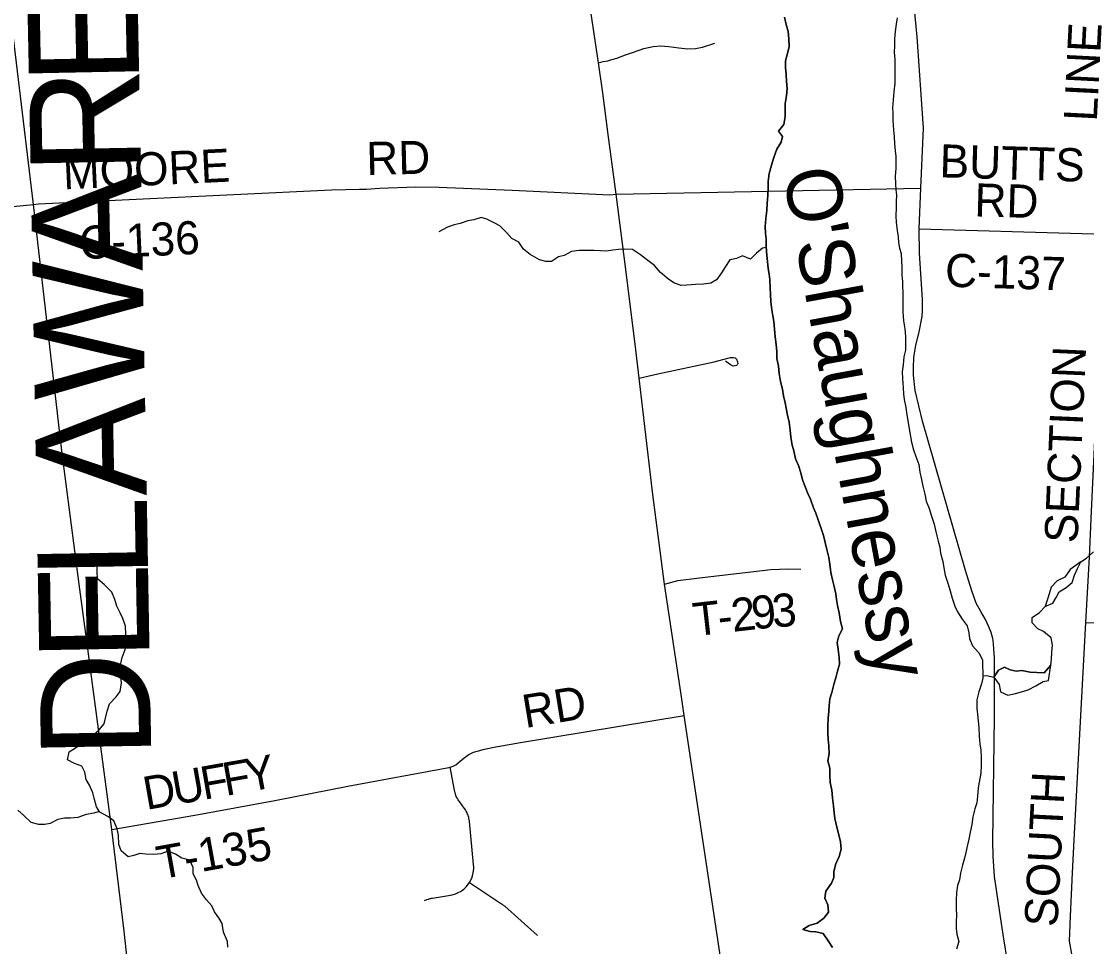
# Model space of a CAD drawing. Extents: x 114843 to 284848, y 317643 to 566895.
# Drawn here: x 158973 to 168629, y 472931 to 481317 of the extents above; entities that cross this region are included whole.
import ezdxf

# ---------------------------------------------------------------- set-up
doc = ezdxf.new("R2010")
doc.units = 0
for name, color, linetype in [('GM_X_County_Road', 7, 'Continuous'), ('GM_X_County_Road_Text', 7, 'Continuous'), ('GM_X_County_Text', 7, 'Continuous'), ('GM_X_Major_Lake', 7, 'Continuous'), ('GM_X_Major_Lake_Text', 7, 'Continuous'), ('GM_X_Major_River', 7, 'Continuous'), ('GM_X_Minor_Lake', 7, 'Continuous'), ('GM_X_Minor_River', 7, 'Continuous'), ('GM_X_State_Route', 7, 'Continuous'), ('GM_X_Township_Road', 7, 'Continuous'), ('GM_X_Township_Road_Text', 7, 'Continuous')]:
    doc.layers.add(name, color=color, linetype=linetype)

msp = doc.modelspace()

# ---------------------------------------------------------------- linework, layer by layer
at = {"layer": 'GM_X_County_Road'}
msp.add_line((164365.2, 479750.2), (167125.8, 479806.3), dxfattribs=at)
for points in [[(159995.6, 472237.1), (159989.5, 472274.8), (159966.4, 472511.4), (159905.9, 473072.7), (159793.2, 473994.7), (159569.3, 475675.8), (159495.8, 476217.3), (159338.5, 477426), (159082.2, 479658.2), (158724.2, 482628.7), (158714, 482659), (158704.8, 482681.5), (158690.1, 482700.8)], [(157972.4, 479547.1), (158895.2, 479640), (159082.2, 479658.2), (159128.7, 479662.1), (161782.7, 479788.9), (162037.7, 479794.5), (162101.2, 479797.4), (162218.7, 479806.1), (162549.4, 479817.5), (162760.8, 479813.2), (163422.3, 479788.3), (164307.3, 479746), (164365.2, 479750.2)], [(167111, 479436.1), (168587.6, 479394.1), (168791.8, 479386.9)], [(168500.2, 472699.2), (168497.8, 472847.6), (168474.7, 472980.9), (168482.2, 473208.2), (168501.7, 473600.7), (168517.9, 473957), (168621, 475870.1), (168654.6, 476460.9), (168672.4, 476876.8), (168748.3, 478484), (168750.7, 478520.2), (168757.1, 478618.5), (168791.8, 479386.9)]]:
    msp.add_lwpolyline(points, dxfattribs=at)
at = {"layer": 'GM_X_Major_Lake'}
for points in [[(166369, 475687), (166382.9, 475749.2), (166414.8, 475811.4), (166398.6, 475879.5), (166384.3, 475957.6), (166370.1, 476021.7), (166361.9, 476077.7), (166355.7, 476129.8), (166341.5, 476195.9), (166325.3, 476256), (166311.1, 476322.1), (166300.8, 476398.2), (166290.6, 476458.3), (166274.4, 476530.4), (166258.1, 476594.4), (166243.9, 476658.5), (166225.7, 476712.6), (166201.5, 476780.7), (166173.2, 476858.7), (166153, 476908.8), (166124.7, 476986.9), (166102.5, 477038.9), (166080.2, 477093), (166054, 477163), (166037.7, 477225.1), (166017.5, 477291.2), (165991.3, 477353.2), (165975, 477425.4), (165960.8, 477475.4), (165948.6, 477547.5), (165940.4, 477611.6), (165932.1, 477685.8), (165917.9, 477747.9), (165905.7, 477809.9), (165897.5, 477860), (165881.3, 477924.1), (165871.1, 477984.2), (165854.9, 478054.3), (165842.6, 478124.4), (165834.4, 478190.5), (165822.2, 478262.7), (165820, 478322.8), (165815.8, 478388.9), (165805.6, 478459), (165799.3, 478527.2), (165793.1, 478597.3), (165783, 478649.4), (165774.8, 478701.5), (165766.5, 478775.6), (165762.3, 478845.7), (165760.2, 478897.8), (165757.9, 478976), (165751.8, 479026.1), (165741.6, 479078.2), (165737.4, 479140.3), (165731.2, 479194.4), (165725, 479276.5), (165722.8, 479344.7), (165718.6, 479394.8), (165716.4, 479456.9), (165722.2, 479531.1), (165730.1, 479601.2), (165731.9, 479667.4), (165737.7, 479737.5), (165743.5, 479801.7), (165743.3, 479865.8), (165751.1, 479938), (165773, 480012.2), (165794.8, 480082.4), (165820.7, 480158.7), (165858.6, 480220.9), (165872.5, 480273), (165836.2, 480323), (165884.2, 480383.3), (165896, 480453.5), (165895.9, 480503.6), (165897.7, 480571.7), (165907.5, 480641.9), (165913.3, 480708.1), (165909.1, 480774.2), (165904.9, 480834.3), (165900.7, 480898.4), (165900.6, 480958.6), (165916.4, 481024.8), (165932.3, 481088.9), (165930.1, 481159.1), (165923.8, 481225.2), (165905.6, 481289.3), (165889.4, 481353.4)], [(166910.1, 481348), (166902.3, 481289.8), (166894.4, 481225.7), (166888.6, 481157.5), (166886.8, 481091.4), (166884.9, 481037.2), (166889.1, 480971.1), (166891.3, 480909), (166891.6, 480808.8), (166889.8, 480756.7), (166882, 480676.5), (166876.2, 480606.3), (166870.4, 480534.1), (166872.5, 480484), (166872.7, 480417.9), (166877, 480333.7), (166885.2, 480271.6), (166887.4, 480205.5), (166893.6, 480143.3), (166899.7, 480091.2), (166899.9, 480035.1), (166898.1, 479983), (166894.2, 479912.8), (166896.4, 479844.7), (166898.6, 479790.6), (166904.8, 479740.5), (166902.9, 479684.4), (166901.1, 479632.3), (166899.3, 479550.1), (166903.5, 479498), (166911.7, 479421.8), (166919.9, 479363.7), (166924.1, 479313.6), (166932.2, 479261.6), (166946.4, 479211.5), (166950.6, 479143.3), (166954.8, 479091.2), (166955, 479019.1), (166961.2, 478957), (166961.6, 478822.7), (166963.7, 478768.6), (166962, 478688.4), (166968.2, 478602.3), (166980.5, 478530.1), (166986.7, 478460), (166987.1, 478335.8), (166973.2, 478275.6), (166965.4, 478203.4), (166957.5, 478141.3), (166959.7, 478079.1), (166966, 477997), (166968.2, 477940.9), (166974.3, 477888.8), (166988.6, 477818.7), (166998.8, 477750.6), (167011, 477682.5), (167019.2, 477624.4), (167031.4, 477554.3), (167041.6, 477502.2), (167059.9, 477434.1), (167080.1, 477372), (167108.4, 477299.9), (167116.6, 477231.8), (167132.8, 477163.8), (167145, 477103.7), (167161.3, 477031.6), (167175.5, 476967.5), (167201.8, 476903.4), (167224, 476831.3)], [(167224, 476831.3), (167246.3, 476761.2), (167258.5, 476707.2), (167270.7, 476655.1), (167282.8, 476605), (167297, 476553), (167305.2, 476496.9), (167325.5, 476422.8), (167335.7, 476364.7), (167345.9, 476298.6), (167370.2, 476224.5), (167390.4, 476156.5), (167408.7, 476088.4), (167434.9, 476016.3), (167457.1, 475964.3), (167499.4, 475900.3), (167545.7, 475838.3), (167562, 475774.2), (167568.1, 475724.1), (167594.4, 475658.1), (167652.7, 475594.1), (167685, 475530.1), (167685.1, 475472), (167689.3, 475417.9), (167687.5, 475363.8), (167675.6, 475313.7), (167651.7, 475239.5), (167633.9, 475167.3), (167634.1, 475089.2), (167638.3, 475037.1), (167646.5, 474975), (167652.6, 474916.9), (167654.9, 474838.8), (167661.1, 474766.7), (167669.2, 474714.6), (167671.4, 474642.5), (167671.6, 474576.4), (167669.8, 474504.3), (167656, 474422.2), (167646.1, 474370), (167640.3, 474295.9), (167632.5, 474235.8), (167614.6, 474179.7), (167596.8, 474107.5), (167586.9, 474037.4), (167573.1, 473969.3), (167561.2, 473905.2), (167549.3, 473853), (167533.5, 473784.9), (167521.6, 473734.8), (167503.7, 473668.7), (167485.9, 473598.5), (167476, 473536.4), (167458.1, 473486.3), (167450.3, 473422.2), (167446.5, 473350.1), (167446.7, 473280), (167448.8, 473211.9), (167447, 473161.9), (167447.2, 473095.8), (167451.3, 473043.7), (167471.5, 472979.7), (167449.7, 472907.6)], [(166324.6, 472924.8), (166286.4, 472984.8), (166242.1, 473050.7), (166173.9, 473066.6), (166123.7, 473068.5), (166057.5, 473086.3), (166113.5, 473122.5), (166185.7, 473144.7), (166245.7, 473188.9), (166289.7, 473243.1), (166281.5, 473309.2), (166257.2, 473371.2), (166265.1, 473435.3), (166317, 473505.5), (166336.9, 473559.6), (166336.8, 473611.7), (166354.6, 473681.8), (166386.5, 473748), (166402.4, 473816.1), (166398.2, 473882.2), (166382, 473946.3), (166363.7, 474014.3), (166345.5, 474092.4), (166339.3, 474144.5), (166333.1, 474208.5), (166324.9, 474280.6), (166318.7, 474348.7), (166304.4, 474418.8), (166300.3, 474480.9), (166302.1, 474549), (166283.8, 474615), (166293.7, 474683.2), (166293.5, 474747.3), (166287.3, 474811.4), (166283.1, 474863.4), (166283, 474929.5), (166284.8, 475001.7), (166290.6, 475065.8), (166294.5, 475115.9), (166302.3, 475178), (166318.2, 475234.1), (166338, 475306.3), (166359.9, 475378.5), (166371.8, 475428.6), (166387.6, 475490.8), (166385.5, 475552.9), (166377.2, 475623), (166369, 475687)]]:
    msp.add_lwpolyline(points, dxfattribs=at)
at = {"layer": 'GM_X_Major_River'}
for points in [[(165889.4, 481353.4), (165905.6, 481289.3), (165923.8, 481225.2), (165930.1, 481159.1), (165932.3, 481088.9), (165916.4, 481024.8), (165900.6, 480958.6), (165900.7, 480898.4), (165904.9, 480834.3), (165909.1, 480774.2), (165913.3, 480708.1), (165907.5, 480641.9), (165897.7, 480571.7), (165895.9, 480503.6), (165896, 480453.5), (165884.2, 480383.3), (165836.2, 480323), (165872.5, 480273), (165858.6, 480220.9), (165820.7, 480158.7), (165794.8, 480082.4), (165773, 480012.2), (165751.1, 479938), (165743.3, 479865.8), (165743.5, 479801.7), (165737.7, 479737.5), (165731.9, 479667.4), (165730.1, 479601.2), (165722.2, 479531.1), (165716.4, 479456.9), (165718.6, 479394.8), (165722.8, 479344.7), (165725, 479276.5), (165731.2, 479194.4), (165737.4, 479140.3), (165741.6, 479078.2), (165751.8, 479026.1), (165757.9, 478976), (165760.2, 478897.8), (165762.3, 478845.7), (165766.5, 478775.6), (165774.8, 478701.5), (165783, 478649.4), (165793.1, 478597.3), (165799.3, 478527.2), (165805.6, 478459), (165815.8, 478388.9), (165820, 478322.8), (165822.2, 478262.7), (165834.4, 478190.5), (165842.6, 478124.4), (165854.9, 478054.3), (165871.1, 477984.2), (165881.3, 477924.1), (165897.5, 477860), (165905.7, 477809.9), (165917.9, 477747.9), (165932.1, 477685.8), (165940.4, 477611.6), (165948.6, 477547.5), (165960.8, 477475.4), (165975, 477425.4), (165991.3, 477353.2), (166017.5, 477291.2), (166037.7, 477225.1), (166054, 477163), (166080.2, 477093), (166102.5, 477038.9), (166124.7, 476986.9), (166153, 476908.8), (166173.2, 476858.7), (166201.5, 476780.7), (166225.7, 476712.6), (166243.9, 476658.5), (166258.1, 476594.4), (166274.4, 476530.4), (166290.6, 476458.3), (166300.8, 476398.2), (166311.1, 476322.1), (166325.3, 476256), (166341.5, 476195.9), (166355.7, 476129.8), (166361.9, 476077.7), (166370.1, 476021.7), (166384.3, 475957.6), (166398.6, 475879.5), (166414.8, 475811.4), (166382.9, 475749.2), (166369, 475687)], [(166910.1, 481348), (166902.3, 481289.8), (166894.4, 481225.7), (166888.6, 481157.5), (166886.8, 481091.4), (166884.9, 481037.2), (166889.1, 480971.1), (166891.3, 480909), (166891.6, 480808.8), (166889.8, 480756.7), (166882, 480676.5), (166876.2, 480606.3), (166870.4, 480534.1), (166872.5, 480484), (166872.7, 480417.9), (166877, 480333.7), (166885.2, 480271.6), (166887.4, 480205.5), (166893.6, 480143.3), (166899.7, 480091.2), (166899.9, 480035.1), (166898.1, 479983), (166894.2, 479912.8), (166896.4, 479844.7), (166898.6, 479790.6), (166904.8, 479740.5), (166902.9, 479684.4), (166901.1, 479632.3), (166899.3, 479550.1), (166903.5, 479498), (166911.7, 479421.8), (166919.9, 479363.7), (166924.1, 479313.6), (166932.2, 479261.6), (166946.4, 479211.5), (166950.6, 479143.3), (166954.8, 479091.2), (166955, 479019.1), (166961.2, 478957), (166961.6, 478822.7), (166963.7, 478768.6), (166962, 478688.4), (166968.2, 478602.3), (166980.5, 478530.1), (166986.7, 478460), (166987.1, 478335.8), (166973.2, 478275.6), (166965.4, 478203.4), (166957.5, 478141.3), (166959.7, 478079.1), (166966, 477997), (166968.2, 477940.9), (166974.3, 477888.8), (166988.6, 477818.7), (166998.8, 477750.6), (167011, 477682.5), (167019.2, 477624.4), (167031.4, 477554.3), (167041.6, 477502.2), (167059.9, 477434.1), (167080.1, 477372), (167108.4, 477299.9), (167116.6, 477231.8), (167132.8, 477163.8), (167145, 477103.7), (167161.3, 477031.6), (167175.5, 476967.5), (167201.8, 476903.4), (167224, 476831.3)], [(167224, 476831.3), (167246.3, 476761.2), (167258.5, 476707.2), (167270.7, 476655.1), (167282.8, 476605), (167297, 476553), (167305.2, 476496.9), (167325.5, 476422.8), (167335.7, 476364.7), (167345.9, 476298.6), (167370.2, 476224.5), (167390.4, 476156.5), (167408.7, 476088.4), (167434.9, 476016.3), (167457.1, 475964.3), (167499.4, 475900.3), (167545.7, 475838.3), (167562, 475774.2), (167568.1, 475724.1), (167594.4, 475658.1), (167652.7, 475594.1), (167685, 475530.1), (167685.1, 475472), (167689.3, 475417.9), (167687.5, 475363.8), (167675.6, 475313.7), (167651.7, 475239.5), (167633.9, 475167.3), (167634.1, 475089.2), (167638.3, 475037.1), (167646.5, 474975), (167652.6, 474916.9), (167654.9, 474838.8), (167661.1, 474766.7), (167669.2, 474714.6), (167671.4, 474642.5), (167671.6, 474576.4), (167669.8, 474504.3), (167656, 474422.2), (167646.1, 474370), (167640.3, 474295.9), (167632.5, 474235.8), (167614.6, 474179.7), (167596.8, 474107.5), (167586.9, 474037.4), (167573.1, 473969.3), (167561.2, 473905.2), (167549.3, 473853), (167533.5, 473784.9), (167521.6, 473734.8), (167503.7, 473668.7), (167485.9, 473598.5), (167476, 473536.4), (167458.1, 473486.3), (167450.3, 473422.2), (167446.5, 473350.1), (167446.7, 473280), (167448.8, 473211.9), (167447, 473161.9), (167447.2, 473095.8), (167451.3, 473043.7), (167471.5, 472979.7), (167449.7, 472907.6)], [(166369, 475687), (166377.2, 475623), (166385.5, 475552.9), (166387.6, 475490.8), (166371.8, 475428.6), (166359.9, 475378.5), (166338, 475306.3), (166318.2, 475234.1), (166302.3, 475178), (166294.5, 475115.9), (166290.6, 475065.8), (166284.8, 475001.7), (166283, 474929.5), (166283.1, 474863.4), (166287.3, 474811.4), (166293.5, 474747.3), (166293.7, 474683.2), (166283.8, 474615), (166302.1, 474549), (166300.3, 474480.9), (166304.4, 474418.8), (166318.7, 474348.7), (166324.9, 474280.6), (166333.1, 474208.5), (166339.3, 474144.5), (166345.5, 474092.4), (166363.7, 474014.3), (166382, 473946.3), (166398.2, 473882.2), (166402.4, 473816.1), (166386.5, 473748), (166354.6, 473681.8), (166336.8, 473611.7), (166336.9, 473559.6), (166317, 473505.5), (166265.1, 473435.3), (166257.2, 473371.2), (166281.5, 473309.2), (166289.7, 473243.1), (166245.7, 473188.9), (166185.7, 473144.7), (166113.5, 473122.5), (166057.5, 473086.3), (166123.7, 473068.5), (166173.9, 473066.6), (166242.1, 473050.7), (166286.4, 472984.8), (166324.6, 472924.8)]]:
    msp.add_lwpolyline(points, dxfattribs=at)
at = {"layer": 'GM_X_Minor_Lake'}
for points in [[(168252.7, 476015.4), (168322.7, 476043.8), (168352.6, 476096), (168380.4, 476146.3), (168442.4, 476186.6), (168498.3, 476232.9), (168520, 476297.2), (168545.8, 476357.4), (168577.6, 476419.7)], [(168577.6, 476419.7), (168479.7, 476349.1), (168431.9, 476278.8), (168361.9, 476246.4), (168308, 476188), (168292.2, 476137.9), (168252.7, 476015.4)], [(167788.4, 475372.2), (167836.8, 475308.2), (167847.2, 475240.1), (167913.4, 475210.4), (167985.5, 475226.7), (168037.6, 475241), (168099.7, 475259.2), (168167.7, 475295.6), (168233.6, 475334), (168283.7, 475344.2), (168305.1, 475482.6)], [(168305.1, 475482.6), (168245.3, 475414.2), (168177.1, 475415.9), (168117, 475419.6), (168042.8, 475435.4), (167990.7, 475427.1), (167936.5, 475438.9), (167884.3, 475464.7), (167830.3, 475438.5), (167788.4, 475372.2)]]:
    msp.add_lwpolyline(points, dxfattribs=at)
at = {"layer": 'GM_X_Minor_River'}
for points in [[(165725.6, 479268.5), (165690.4, 479261.9), (165636.5, 479215.6), (165580.6, 479161.2), (165510.3, 479193), (165456.3, 479168.7), (165394.2, 479154.4), (165354.4, 479096.1), (165318.5, 479037.8), (165274.7, 478973.5), (165222.7, 478943.2), (165156.6, 478934.9), (165082.5, 478930.6), (165004.3, 478926.2), (164954.2, 478924), (164892, 478943.8), (164841.7, 478977.7), (164767.3, 479039.5), (164710.9, 479105.4), (164638.5, 479157.2), (164586.1, 479201.1), (164511.8, 479248.9), (164439.6, 479252.6), (164385.5, 479250.4), (164333.4, 479244.1), (164277.3, 479233.9), (164221.2, 479235.6), (164165, 479239.4), (164102.9, 479239.2), (164028.7, 479240.8), (163960.6, 479232.5), (163892.6, 479194.2), (163842.5, 479181.9), (163778.6, 479141.6), (163726.5, 479141.3), (163670.3, 479155.1), (163585.8, 479204.9), (163525.5, 479252.7), (163481.1, 479314.7), (163418.8, 479348.5), (163372.5, 479400.4), (163310.1, 479462.3), (163257.8, 479492.2), (163193.5, 479524), (163139.3, 479537.8), (163073.3, 479519.4), (163019.2, 479509.2), (162949.1, 479484.8), (162895.1, 479472.6), (162837, 479450.3), (162757, 479407.8)], [(167688.2, 475386.1), (167724.2, 475387.9), (167788.4, 475372.2), (167830.3, 475438.5), (167884.3, 475464.7), (167936.5, 475438.9), (167990.7, 475427.1), (168042.8, 475435.4), (168117, 475419.6), (168177.1, 475415.9), (168245.3, 475414.2), (168305.1, 475482.6), (168310.9, 475536.7), (168314.6, 475600.8), (168318.4, 475663), (168308.1, 475729.1), (168237.7, 475786.9), (168185.4, 475810.7), (168135.1, 475864.6), (168134.9, 475914.7), (168200.8, 475959.1), (168252.7, 476015.4), (168322.7, 476043.8), (168352.6, 476096), (168380.4, 476146.3), (168442.4, 476186.6), (168498.3, 476232.9), (168520, 476297.2), (168545.8, 476357.4), (168577.6, 476419.7), (168627.6, 476452), (168691.5, 476510.4)], [(160845.3, 472926.9), (160841, 472979), (160806.6, 473063), (160792.2, 473141), (160763.9, 473193), (160723.6, 473246.9), (160699.3, 473300.9), (160651, 473356.8), (160604.6, 473416.7), (160576.2, 473484.7), (160560, 473534.7), (160531.7, 473590.6), (160531.4, 473648.7), (160499, 473716.7), (160428.8, 473732.4), (160370.5, 473770.3), (160304.3, 473798), (160236.2, 473771.7), (160172.1, 473767.4), (160099.9, 473769.1), (160045.8, 473774.9), (159993.7, 473756.7), (159941.7, 473746.4), (159877.3, 473800.2), (159857, 473856.2), (159854.6, 473940.4), (159842.3, 474000.4), (159811.9, 474072.4), (159757.7, 474112.3), (159683.3, 474150), (159653, 474200), (159632.7, 474276), (159620.4, 474326), (159592, 474394), (159559.7, 474446), (159549.4, 474512.1), (159521.1, 474566), (159454.9, 474589.8), (159392.6, 474625.6), (159406.3, 474697.8), (159474.3, 474740.1), (159544.3, 474778.5), (159610.2, 474836.9), (159676.1, 474893.3), (159723.9, 474951.6), (159735.7, 475001.7), (159751.5, 475065.9), (159773.2, 475132.1), (159831.1, 475194.5), (159868.9, 475244.7), (159880.6, 475320.9), (159872.3, 475397), (159870.1, 475447.1), (159873.9, 475497.2), (159885.6, 475551.4), (159913.4, 475623.6), (159931.1, 475689.8), (159920.8, 475761.9), (159916.5, 475836.1), (159894.1, 475906.1), (159867.8, 475956.1), (159839.5, 476018.1), (159821.2, 476078.1), (159792.8, 476144.1), (159726.4, 476210), (159662, 476265.8), (159659.7, 476332), (159661.5, 476386.1)], [(159678.9, 474157.4), (159631.2, 474141.8), (159561.1, 474129.5), (159485.1, 474101.1), (159419, 474094.8), (159364.8, 474096.6), (159302.8, 474084.3), (159234.8, 474048), (159184.7, 474039.7), (159130.6, 474037.5), (159062.3, 474055.2), (158993.9, 474123.1), (158941.6, 474166.9)]]:
    msp.add_lwpolyline(points, dxfattribs=at)
at = {"layer": 'GM_X_State_Route'}
for points in [[(165414.5, 472143.8), (165392.8, 472291.6), (164982.2, 475026), (164954.6, 475217), (164801.1, 476217.8), (164696.6, 477030.4), (164572.1, 478083.3), (164536.4, 478391.9), (164437.4, 479185.8), (164365.2, 479750.2), (164291.9, 480290.8), (164242.8, 480668.5), (164204.2, 480939.5), (164039.6, 482054.5), (163926.7, 482826.3), (163709.5, 484303.6), (163389.6, 486352.5), (163254.7, 487193.7), (163187.9, 487618.4)], [(167111, 479436.1), (167125.8, 479806.3), (167150.4, 480349.5), (167093.2, 481175.8), (167057.5, 481554.2)], [(167782.1, 475704.5), (167779.5, 475723.5), (167764.7, 475779), (167743.7, 475830.3), (167712.4, 475896), (167670.6, 475969.8), (167628.9, 476043.7), (167587, 476154.6), (167532.1, 476339.6), (167142, 477693.5), (167073.5, 477972.1), (167060.2, 478109.9), (167058.6, 478177.2), (167063.1, 478273.4), (167082.1, 478378.7), (167110.5, 478503.1), (167137.3, 478640.8), (167141.7, 478698), (167140.7, 478794.6), (167112.8, 479214.7), (167111, 479436.1)], [(167793.9, 475026.8), (167793.1, 475548.5), (167788.4, 475626.7), (167786, 475676.1), (167782.1, 475704.5)], [(167793.9, 473571.4), (167780.9, 473752.4), (167779.9, 473887.6), (167794, 475011.1), (167793.9, 475026.8)], [(167879.4, 473002.9), (167847.9, 473203.1), (167794.2, 473566.2), (167793.9, 473571.4)], [(167912.2, 472797.2), (167911.6, 472797.6), (167879.4, 473002.9)]]:
    msp.add_lwpolyline(points, dxfattribs=at)
at = {"layer": 'GM_X_Township_Road'}
for points in [[(164204.2, 480939.5), (164247.7, 480953.9), (164287.7, 480959.3), (164316.3, 480966.6), (164370.4, 480983), (164449.7, 481014.2), (164511.2, 481035.8), (164615, 481069.5), (164700.2, 481088), (164769.7, 481095.4), (164841.2, 481090), (164933.6, 481077.7), (165013.1, 481066.4), (165083.5, 481070.9), (165147, 481081.3), (165259.9, 481120.2)], [(164572.1, 478083.3), (164740.6, 478123.3), (165252.1, 478231.5), (165330.4, 478251.3), (165401.8, 478269.3), (165428.3, 478271), (165444, 478266.2), (165455.3, 478255.9), (165464.9, 478231.7), (165466.7, 478216.3), (165462.3, 478204.5), (165455.1, 478198.5), (165441.9, 478194.1), (165425, 478193.3), (165400, 478203.8), (165378.8, 478219.1), (165356.4, 478237.8)], [(164801.1, 476217.8), (164923.7, 476250), (165120.3, 476272.9), (165766.3, 476348.5), (165924.3, 476355), (166039.4, 476351.8)], [(168621, 475870.1), (169248, 475851.9), (169473.7, 475852.3), (169593.8, 475853.1), (169659.8, 475849.6), (169699.4, 475852.6), (169733.6, 475864.7), (169746.7, 475876.7), (169759.8, 475896.6), (169766.2, 475920.4), (169771.2, 475960), (169771.9, 476048.5), (169765.7, 476121)], [(159793.2, 473994.7), (160546.5, 474122.2), (161270.6, 474256.8), (161932.8, 474385.6), (162848.4, 474554.3), (162860.2, 474558.3), (162885.5, 474567), (162910.1, 474579.5), (162950.4, 474612.4), (162986.2, 474643.4), (163028.3, 474673.7), (163071.3, 474694.3), (163115.5, 474706.9), (163172.3, 474721.4), (163275.2, 474742.4), (163496.8, 474780.1), (164982.2, 475026)], [(162628.6, 473349.9), (162649.8, 473359), (162662.2, 473363.3), (162668.3, 473365.2), (162675.2, 473367), (162683.4, 473369), (162690.4, 473370.4), (162698.3, 473371.8), (162864, 473399.3), (162877.3, 473401.8), (162885.8, 473403.8), (162900.6, 473408.1), (162912.7, 473412.3), (162926, 473417.8), (162938.9, 473424), (162952.1, 473431.3), (162963.6, 473438.7), (162982.2, 473452.4), (162991.6, 473460.5), (163003.8, 473472.4), (163035.1, 473512.2), (163055.7, 473552.6), (163063.1, 473574.2), (163069.5, 473601), (163072.4, 473622.8), (163073.3, 473638.2), (163073.2, 473653.7), (163071.5, 473675.2), (163034.6, 474065.4), (163033.6, 474073.1), (163032.6, 474079.8), (163030.2, 474091.9), (163027.9, 474101.4), (163024.9, 474112.1), (163021.6, 474122), (163017.6, 474132.4), (163013.8, 474141.4), (163010.1, 474149.2), (163005.2, 474158.6), (163001.7, 474164.7), (162997.3, 474171.9), (162991.9, 474180.1), (162986.7, 474187.4), (162943.4, 474246.1), (162939.3, 474251.8), (162932.4, 474262.3), (162925, 474275), (162918.7, 474287.3), (162912.6, 474301.1), (162907.3, 474315.5), (162903.9, 474326.4), (162900.7, 474338.9), (162898.5, 474349.8), (162860.2, 474558.3)], [(163035.1, 473512.2), (163326.1, 473318.9), (163330.1, 473316.2), (163334.4, 473313.2), (163337.9, 473310.6), (163341.4, 473307.9), (163344.8, 473305.2), (163349.6, 473301.4), (163354.4, 473297.1), (163652.8, 473032.3)]]:
    msp.add_lwpolyline(points, dxfattribs=at)

# ---------------------------------------------------------------- texts
at = {"layer": 'GM_X_County_Road_Text'}
for s, rotation, p in [('LINE', 87.09926, (168720.9, 480405.4)), ('RD', 1.39769, (162103.2, 479923.2)), ('MOORE', 2.69473, (159356.3, 479793.5)), ('BUTTS', 358.24367, (167292.6, 479903.7)), ('RD', 358.43684, (167609, 479549.5)), ('C-136', 2.61469, (159504.4, 479160.2)), ('C-137', 358.21013, (167342.3, 478913)), ('SECTION', 87.48644, (168545.7, 476584.2)), ('SOUTH', 87.10621, (168364.1, 473106.2))]:
    msp.add_text(s, height=300, rotation=rotation, dxfattribs=at).set_placement(p)
at = {"layer": 'GM_X_County_Text'}
for s, rotation, p in [('E', 91.15778, (160042.6, 480755.1)), ('R', 91.07372, (160057.9, 479938.4)), ('A', 91.02752, (160073.8, 479055)), ('W', 91.0122, (160094.2, 477901.3)), ('A', 91.01149, (160109.7, 477018.8)), ('L', 91.01143, (160122.9, 476272.3)), ('E', 91.01143, (160136.1, 475525.8)), ('D', 91.01154, (160151.7, 474643.3))]:
    msp.add_text(s, height=1000, rotation=rotation, dxfattribs=at).set_placement(p)
at = {"layer": 'GM_X_Major_Lake_Text'}
msp.add_text("O'Shaughnessy", height=499.854, rotation=280.41998, dxfattribs=at).set_placement((165873.2, 479951.3))
at = {"layer": 'GM_X_Township_Road_Text'}
for s, rotation, p in [('2', 6.39753, (165422.4, 475783.8)), ('9', 6.19869, (165605.8, 475804.4)), ('3', 3.81793, (165786.2, 475824.1)), ('T', 6.45356, (165077.1, 475744.8)), ('-', 6.44192, (165300.1, 475770)), ('RD', 9.30905, (163540.4, 474911.8)), ('F', 9.98967, (160825.2, 474296.6)), ('Y', 10.57462, (161027.8, 474332.3)), ('U', 9.98107, (160365.8, 474215.7)), ('F', 9.97852, (160625.8, 474261.5)), ('D', 9.97881, (160105.8, 474170)), ('T-135', 10.28982, (160229.9, 473540.3))]:
    msp.add_text(s, height=300, rotation=rotation, dxfattribs=at).set_placement(p)

doc.saveas('drawing.dxf')
